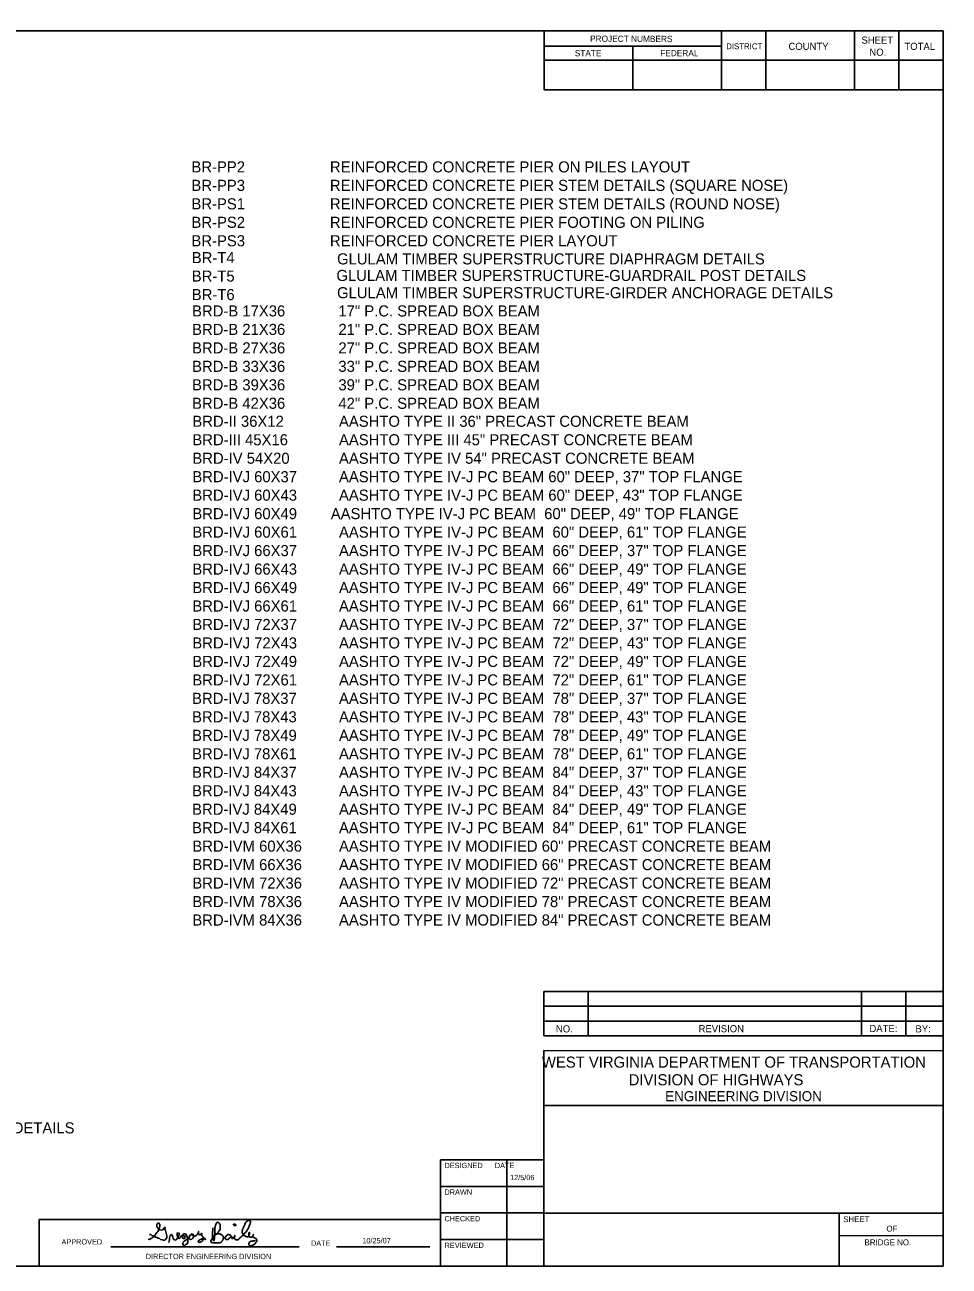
# Model space of a CAD drawing. Extents: x 3383 to 3913, y -1011 to -674.
# Drawn here: x 3662.6 to 3912.7, y -1010.2 to -674.2 of the extents above; entities that cross this region are included whole.
import ezdxf

# ---------------------------------------------------------------- set-up
doc = ezdxf.new("R2010")
doc.units = 0
for name, color, linetype in [('14', 7, 'Continuous'), ('63', 7, 'Continuous'), ('Level 1', 7, 'Continuous'), ('Level 14', 7, 'Continuous'), ('text', 7, 'Continuous')]:
    doc.layers.add(name, color=color, linetype=linetype)

msp = doc.modelspace()

# ---------------------------------------------------------------- linework, layer by layer
at = {"layer": '14'}
for p, q in [((3407.12, -675.81), (3911.13, -675.83)), ((3803.13, -691.83), (3803.13, -675.81)), ((3851.12, -691.81), (3851.13, -675.81)), ((3863.12, -691.81), (3863.13, -675.81)), ((3887.13, -691.81), (3887.13, -675.83)), ((3899.12, -691.81), (3899.13, -675.83)), ((3911.13, -675.83), (3911.13, -1010.23)), ((3911.13, -691.81), (3911.13, -675.83)), ((3851.14, -680.02), (3803.14, -680.02)), ((3827.13, -691.81), (3827.14, -680.02)), ((3911.12, -683.83), (3803.13, -683.81)), ((3911.13, -691.81), (3803.13, -691.83)), ((3911.05, -935.91), (3803.03, -935.91)), ((3803.05, -935.91), (3803.05, -947.91)), ((3815.03, -935.91), (3815.05, -947.89)), ((3889.03, -935.89), (3889.05, -947.89)), ((3901.05, -935.89), (3901.05, -947.89)), ((3911.05, -939.89), (3803.05, -939.89)), ((3911.05, -943.91), (3803.03, -943.91)), ((3911.03, -947.89), (3803.05, -947.91)), ((3911.05, -951.91), (3803.05, -951.89)), ((3803.05, -951.89), (3803.05, -1010.23)), ((3911.05, -966.73), (3803.05, -966.72)), ((3803.08, -981.43), (3775.09, -981.43)), ((3775.09, -981.43), (3775.09, -1010.23)), ((3793.09, -981.43), (3793.08, -1010.23)), ((3803.08, -988.63), (3775.08, -988.63)), ((3803.08, -995.83), (3775.08, -995.83)), ((3911.03, -995.91), (3803.05, -995.89)), ((3882.93, -995.83), (3882.93, -1010.23)), ((3803.08, -1003.03), (3775.08, -1003.03)), ((3911.05, -1001.99), (3883.05, -1001.97)), ((3911.13, -1010.23), (3407.09, -1010.22))]:
    msp.add_line(p, q, dxfattribs=at)
at = {"layer": '63'}
msp.add_line((3912.73, -674.23), (3912.73, -674.23), dxfattribs=at)
at = {"layer": 'Level 1'}
for p, q in [((3685.9, -1005.04), (3736.86, -1005.04)), ((3746.93, -1005.04), (3772.23, -1005.04))]:
    msp.add_line(p, q, dxfattribs=at)
for points in [[(3721.88, -1001.67), (3721.98, -1001.51), (3722.08, -1001.36), (3722.18, -1001.21), (3722.3, -1001.08), (3722.45, -1000.98), (3722.57, -1000.84), (3722.67, -1000.68), (3722.75, -1000.51), (3722.87, -1000.34), (3722.97, -1000.17), (3723.04, -1000.01), (3723.14, -999.82), (3723.22, -999.64), (3723.31, -999.45), (3723.37, -999.28), (3723.44, -999.12), (3723.51, -998.95), (3723.56, -998.77), (3723.62, -998.6), (3723.66, -998.41), (3723.69, -998.23), (3723.66, -998.04), (3723.54, -997.91), (3723.37, -997.84), (3723.19, -997.81), (3723.02, -997.91), (3722.87, -998.01), (3722.7, -998.08), (3722.57, -998.2), (3722.47, -998.35), (3722.37, -998.5), (3722.23, -998.63), (3722.2, -998.82), (3722.13, -998.98), (3722.06, -999.15), (3721.96, -999.3), (3721.9, -999.47), (3721.8, -999.62), (3721.76, -999.8), (3721.66, -999.96), (3721.63, -1000.14), (3721.56, -1000.32), (3721.49, -1000.51), (3721.43, -1000.68), (3721.43, -1000.86), (3721.43, -1001.05), (3721.46, -1001.23), (3721.54, -1001.4), (3721.61, -1001.58), (3721.7, -1001.75), (3721.83, -1001.87), (3722, -1001.93), (3722.15, -1002.05), (3722.33, -1002.08), (3722.5, -1002.19), (3722.67, -1002.25), (3722.87, -1002.27), (3723.05, -1002.27), (3723.15, -1002.12), (3723.26, -1001.97), (3723.34, -1001.78), (3723.41, -1001.6), (3723.42, -1001.41), (3723.47, -1001.21), (3723.34, -1001.1), (3723.27, -1001.28), (3723.2, -1001.45), (3723.2, -1001.63), (3723.2, -1001.82), (3723.2, -1002), (3723.27, -1002.19), (3723.44, -1002.29), (3723.61, -1002.35), (3723.79, -1002.37), (3723.98, -1002.37), (3724.14, -1002.3), (3724.24, -1002.14), (3724.36, -1002), (3724.45, -1001.82), (3724.5, -1001.63), (3724.41, -1001.82), (3724.35, -1001.98), (3724.28, -1002.15), (3724.35, -1002.32), (3724.51, -1002.4), (3724.68, -1002.49), (3724.8, -1002.62), (3724.98, -1002.67), (3725.17, -1002.74), (3725.28, -1002.87), (3725.35, -1003.04), (3725.42, -1003.21), (3725.42, -1003.39), (3725.38, -1003.58), (3725.25, -1003.69), (3725.15, -1003.85), (3725.02, -1004), (3724.92, -1004.15), (3724.75, -1004.26), (3724.61, -1004.38), (3724.45, -1004.48), (3724.28, -1004.58), (3724.13, -1004.68), (3723.93, -1004.7), (3723.74, -1004.72), (3723.56, -1004.72), (3723.39, -1004.62), (3723.29, -1004.47), (3723.26, -1004.28), (3723.27, -1004.1), (3723.32, -1003.91), (3723.42, -1003.74), (3723.54, -1003.61), (3723.71, -1003.54), (3723.88, -1003.48), (3724.06, -1003.44), (3724.24, -1003.44), (3724.43, -1003.41), (3724.61, -1003.41), (3724.8, -1003.38), (3724.98, -1003.34), (3725.08, -1003.31)], [(3695.98, -1002.91), (3696.39, -1002.97), (3696.65, -1002.85), (3696.99, -1002.64), (3697.26, -1002.37), (3697.59, -1002.17), (3697.9, -1001.87), (3698.06, -1001.46), (3698.3, -1001.16), (3698.6, -1000.89), (3698.83, -1000.56), (3699, -1000.19), (3699.07, -999.75), (3699.14, -999.35), (3699.17, -998.95), (3698.93, -998.55), (3698.57, -998.55), (3698.36, -998.85), (3698.3, -999.22), (3698.3, -999.62), (3698.57, -999.89), (3698.8, -1000.22), (3699.14, -1000.43), (3699.57, -1000.46), (3699.94, -1000.39), (3700.18, -1000.09), (3700.41, -999.72), (3700.61, -999.85), (3700.54, -1000.22), (3700.65, -1000.59), (3700.78, -1000.93), (3700.91, -1001.26), (3700.98, -1001.67), (3701.05, -1002.07), (3701.05, -1002.47), (3700.81, -1002.91), (3700.54, -1003.17), (3700.11, -1003.17), (3699.77, -1003.08), (3699.37, -1002.97), (3699.04, -1002.77), (3698.7, -1002.69), (3698.33, -1002.5), (3697.96, -1002.37), (3697.66, -1002.17), (3697.33, -1002.03), (3696.99, -1001.9), (3696.69, -1001.7), (3696.35, -1001.63)], [(3701.59, -1003.81), (3701.69, -1003.43), (3701.74, -1003.06), (3701.79, -1002.69), (3701.86, -1002.32), (3701.99, -1001.95), (3702.21, -1001.65), (3702.5, -1001.87), (3702.67, -1002.37), (3702.73, -1002.74), (3702.97, -1003.01), (3703.45, -1003.19), (3703.72, -1002.94), (3703.96, -1002.64), (3704.17, -1002.35), (3704.29, -1002), (3704.43, -1001.65), (3704.38, -1001.28), (3703.89, -1001.21), (3703.89, -1001.58), (3703.89, -1001.95), (3703.94, -1002.32), (3704.07, -1002.67), (3704.49, -1002.71), (3704.73, -1002.44), (3704.85, -1002.07), (3705.18, -1001.92), (3705.55, -1001.92), (3705.97, -1002.24), (3705.85, -1002.71), (3705.48, -1002.74), (3705.28, -1002.44), (3705.3, -1002.05), (3705.42, -1001.68), (3705.73, -1001.51), (3706.1, -1001.45), (3706.4, -1001.88), (3706.51, -1002.25), (3706.61, -1002.6), (3706.72, -1002.96), (3706.77, -1003.33), (3706.77, -1003.71), (3706.51, -1004.16), (3706.22, -1004.4), (3705.9, -1004.6), (3705.53, -1004.62), (3705.38, -1004.11), (3705.48, -1003.76), (3705.72, -1003.49), (3705.98, -1003.3), (3706.25, -1003.07), (3706.71, -1002.81), (3707.08, -1002.42), (3707.2, -1002.12), (3707.46, -1001.78), (3707.68, -1001.5), (3708.17, -1001.6), (3708.25, -1001.97), (3708.25, -1002.34), (3708.11, -1002.69), (3707.83, -1002.91), (3707.48, -1003.02), (3707.16, -1002.86), (3707.09, -1002.5), (3707.18, -1002.15), (3707.39, -1001.85), (3707.73, -1001.72), (3708.22, -1001.93), (3708.7, -1002.1), (3709.12, -1001.83), (3709.34, -1001.55), (3709.52, -1001.21), (3709.66, -1000.84), (3709.66, -1001.03), (3709.62, -1001.4), (3709.77, -1001.73), (3710.21, -1001.62), (3710.45, -1001.33), (3710.48, -1001.35), (3710.43, -1001.72), (3710.63, -1002.05), (3710.9, -1002.3), (3710.91, -1002.67), (3710.91, -1003.04), (3710.71, -1003.34), (3710.45, -1003.59), (3710.09, -1003.74), (3709.74, -1003.83), (3709.52, -1003.54), (3709.76, -1003.23), (3710.08, -1003.01), (3710.45, -1002.94), (3710.75, -1002.74), (3711.27, -1002.64), (3711.54, -1003.06), (3711.57, -1003.04)], [(3713.45, -999.89), (3713.46, -1000.07), (3713.46, -1000.26), (3713.46, -1000.44), (3713.46, -1000.64), (3713.43, -1000.83), (3713.4, -1001.01), (3713.4, -1001.2), (3713.4, -1001.38), (3713.4, -1001.57), (3713.41, -1001.75), (3713.43, -1001.93), (3713.43, -1002.12), (3713.45, -1002.3), (3713.48, -1002.49), (3713.5, -1002.69), (3713.51, -1002.87), (3713.56, -1003.06), (3713.68, -1003.19), (3713.78, -1003.34), (3713.83, -1003.16), (3713.9, -1002.99), (3713.95, -1002.81), (3713.97, -1002.62), (3713.97, -1002.44), (3713.97, -1002.25), (3713.98, -1002.07), (3713.98, -1001.88), (3714, -1001.7), (3714.02, -1001.51), (3714.03, -1001.33), (3714.03, -1001.15), (3714.03, -1000.96), (3714.03, -1000.78), (3714.03, -1000.59), (3714.03, -1000.41), (3714.03, -1000.22), (3714.05, -1000.04), (3714.08, -999.85), (3714.12, -999.65), (3714.17, -999.47), (3714.22, -999.28), (3714.23, -999.1), (3714.3, -998.93), (3714.37, -998.77), (3714.44, -998.6), (3714.54, -998.43), (3714.7, -998.36), (3714.89, -998.38), (3715.07, -998.43), (3715.19, -998.56), (3715.27, -998.73), (3715.37, -998.88), (3715.46, -999.05), (3715.49, -999.23), (3715.51, -999.42), (3715.51, -999.6), (3715.51, -999.79), (3715.51, -999.97), (3715.51, -1000.16), (3715.48, -1000.34), (3715.37, -1000.49), (3715.24, -1000.61), (3715.12, -1000.74), (3715.06, -1000.91), (3714.96, -1001.06), (3714.85, -1001.21), (3714.79, -1001.38), (3714.64, -1001.48), (3714.47, -1001.57), (3714.32, -1001.68), (3714.15, -1001.78), (3714.02, -1001.9), (3713.88, -1002.03), (3713.78, -1002.19), (3713.65, -1002.3), (3713.55, -1002.45), (3713.45, -1002.6), (3713.31, -1002.76), (3713.21, -1002.91), (3713.14, -1003.07), (3713.04, -1003.23), (3712.98, -1003.39), (3712.94, -1003.58), (3713.01, -1003.74), (3713.18, -1003.81), (3713.36, -1003.83), (3713.55, -1003.88), (3713.73, -1003.91), (3713.92, -1003.93), (3714.1, -1003.93), (3714.3, -1003.93), (3714.49, -1003.93), (3714.67, -1003.93), (3714.85, -1003.93), (3715.04, -1003.93), (3715.22, -1003.93), (3715.41, -1003.93), (3715.54, -1003.8), (3715.71, -1003.73), (3715.86, -1003.63), (3716.01, -1003.49), (3716.08, -1003.33), (3716.15, -1003.16), (3716.25, -1003.01), (3716.31, -1002.84), (3716.36, -1002.66), (3716.4, -1002.47), (3716.4, -1002.29), (3716.28, -1002.15), (3716.15, -1002.03), (3716.01, -1001.9), (3715.89, -1001.75), (3715.73, -1001.65), (3715.56, -1001.55), (3715.37, -1001.51), (3715.19, -1001.48), (3715.01, -1001.45), (3714.8, -1001.45), (3714.6, -1001.45), (3714.42, -1001.45), (3714.23, -1001.41), (3714.23, -1001.41)], [(3719.2, -998.92), (3719.2, -999.1), (3719.33, -999.22), (3719.52, -999.27), (3719.7, -999.25), (3719.73, -999.07), (3719.6, -998.95), (3719.47, -998.82), (3719.28, -998.82), (3719.11, -998.88), (3719.11, -999)], [(3718.68, -1002.89), (3718.71, -1002.71), (3718.71, -1002.52), (3718.71, -1002.34), (3718.56, -1002.2), (3718.43, -1002.07), (3718.33, -1001.92), (3718.17, -1001.82), (3718.02, -1001.72), (3717.86, -1001.65), (3717.67, -1001.65), (3717.49, -1001.72), (3717.35, -1001.83), (3717.2, -1001.95), (3717.07, -1002.07), (3716.97, -1002.22), (3716.9, -1002.39), (3716.8, -1002.54), (3716.73, -1002.71), (3716.85, -1002.84), (3716.97, -1002.97), (3717.17, -1003.02), (3717.35, -1003.02), (3717.54, -1003.02), (3717.71, -1002.96), (3717.82, -1002.81), (3717.94, -1002.67), (3718.06, -1002.52), (3718.23, -1002.42), (3718.43, -1002.42), (3718.63, -1002.44), (3718.8, -1002.5), (3718.96, -1002.57), (3719.11, -1002.67), (3719.3, -1002.67), (3719.35, -1002.49), (3719.4, -1002.3), (3719.42, -1002.1), (3719.42, -1001.92), (3719.35, -1002.08), (3719.31, -1002.27), (3719.31, -1002.45), (3719.31, -1002.64), (3719.33, -1002.82), (3719.5, -1002.91), (3719.67, -1003.01), (3719.85, -1003.06), (3720.04, -1003.07), (3720.22, -1003.07), (3720.4, -1003.04), (3720.56, -1002.94), (3720.66, -1002.77), (3720.79, -1002.66), (3720.89, -1002.49), (3721.03, -1002.37), (3721.18, -1002.27), (3721.31, -1002.14), (3721.44, -1002), (3721.6, -1001.9), (3721.75, -1001.8), (3721.85, -1001.67)]]:
    msp.add_lwpolyline(points, dxfattribs=at)
at = {"layer": 'Level 14'}
for p, q in [((3666.47, -997.6), (3666.47, -1010.22)), ((3775.09, -997.61), (3666.47, -997.6))]:
    msp.add_line(p, q, dxfattribs=at)

# ---------------------------------------------------------------- texts
at = {"layer": '14'}
for s, height, rotation, p in [('PROJECT NUMBERS', 1.6773, 359.8097, (3815.57, -678.82)), ('SHEET', 1.919, 359.8929, (3889.01, -679.32)), ('STATE', 1.675, 0.1193, (3811.44, -682.74)), ('FEDERAL', 1.675, 359.9983, (3834.56, -682.72)), ('DISTRICT', 1.582, 359.907, (3852.41, -680.82)), ('COUNTY', 1.919, 359.9983, (3869.25, -681.01)), ('NO.', 1.925, 359.9983, (3891.15, -682.6)), ('TOTAL', 1.919, 359.9983, (3900.64, -681.01)), ('NO.', 1.925, 359.9983, (3806.33, -946.96)), ('REVISION', 1.925, 359.9983, (3844.92, -946.92)), ('DATE:', 1.925, 359.9983, (3891.16, -946.87)), ('BY:', 1.925, 359.9983, (3903.61, -946.95)), (' WEST VIRGINIA DEPARTMENT OF TRANSPORTATION', 3.0011, 359.9983, (3801.43, -956.5)), ('    DIVISION OF HIGHWAYS', 3.0011, 359.9983, (3821.56, -961.27)), ('ENGINEERING DIVISION', 2.7185, 359.9983, (3835.88, -965.57)), ('DESIGNED      DATE', 1.432, 359.9983, (3776.18, -983.69)), ('12/5/06', 1.432, 359.9983, (3793.92, -986.94)), ('DRAWN', 1.432, 359.9983, (3776.18, -990.89)), ('CHECKED', 1.432, 359.9983, (3776.18, -998.09)), ('SHEET', 1.589, 359.9983, (3884.07, -998.31)), ('OF', 1.604, 359.9983, (3895.75, -1000.87)), ('10/25/07', 1.432, 359.9983, (3753.95, -1004.03)), ('REVIEWED', 1.447, 0.0944, (3776.18, -1005.31)), ('BRIDGE NO.', 1.604, 359.9983, (3889.83, -1004.59))]:
    msp.add_text(s, height=height, rotation=rotation, dxfattribs=at).set_placement(p)
at = {"layer": 'Level 14'}
for s, p in [('APPROVED', (3672.56, -1004.36)), ('DATE', (3740.06, -1004.72)), ('DIRECTOR ENGINEERING DIVISION', (3695.34, -1008.32))]:
    msp.add_text(s, height=1.432, rotation=359.9983, dxfattribs=at).set_placement(p)
at = {"layer": 'text'}
for s, height, p in [('BR-PP2', 3.001, (3707.71, -714.18)), (' REINFORCED CONCRETE PIER ON PILES LAYOUT', 3.0011, (3744.06, -714.18)), ('BR-PP3', 3.001, (3707.71, -719.18)), (' REINFORCED CONCRETE PIER STEM DETAILS (SQUARE NOSE)', 3.0011, (3744.06, -719.18)), ('BR-PS1', 3.001, (3707.71, -724.18)), (' REINFORCED CONCRETE PIER STEM DETAILS (ROUND NOSE)', 3.0011, (3744.06, -724.18)), ('BR-PS2', 3.001, (3707.71, -729.18)), (' REINFORCED CONCRETE PIER FOOTING ON PILING', 3.0011, (3744.06, -729.18)), ('BR-PS3', 3.001, (3707.71, -734.18)), (' REINFORCED CONCRETE PIER LAYOUT', 3.0011, (3744.06, -734.18)), ('BR-T4', 3.001, (3707.8, -738.74)), ('GLULAM TIMBER SUPERSTRUCTURE DIAPHRAGM DETAILS', 3.0011, (3747.11, -739.08)), ('BR-T5', 3.001, (3707.8, -743.74)), ('GLULAM TIMBER SUPERSTRUCTURE-GUARDRAIL POST DETAILS', 3.0011, (3746.94, -743.57)), ('BR-T6', 3.001, (3707.8, -748.74)), ('GLULAM TIMBER SUPERSTRUCTURE-GIRDER ANCHORAGE DETAILS', 3.0011, (3747.11, -748.24)), ('BRD-B 17X36', 3.0011, (3707.88, -753.17)), ('17" P.C. SPREAD BOX BEAM', 3.0011, (3747.47, -753.17)), ('BRD-B 21X36', 3.0011, (3707.88, -758.17)), ('21" P.C. SPREAD BOX BEAM', 3.0011, (3747.47, -758.17)), ('BRD-B 27X36', 3.0011, (3707.88, -763.17)), ('27" P.C. SPREAD BOX BEAM', 3.0011, (3747.47, -763.17)), ('BRD-B 33X36', 3.0011, (3707.88, -768.17)), ('33" P.C. SPREAD BOX BEAM', 3.0011, (3747.47, -768.17)), ('BRD-B 39X36', 3.0011, (3707.88, -773.17)), ('39" P.C. SPREAD BOX BEAM', 3.0011, (3747.47, -773.17)), ('BRD-B 42X36', 3.0011, (3707.88, -778.17)), ('42" P.C. SPREAD BOX BEAM', 3.0011, (3747.47, -778.17)), ('BRD-II 36X12', 3.0011, (3707.95, -783.04)), ('AASHTO TYPE II 36" PRECAST CONCRETE BEAM', 3.0011, (3747.63, -783.04)), ('BRD-III 45X16', 3.0011, (3707.95, -788.04)), ('AASHTO TYPE III 45" PRECAST CONCRETE BEAM', 3.0011, (3747.63, -788.04)), ('BRD-IV 54X20', 3.0011, (3707.95, -793.04)), ('AASHTO TYPE IV 54" PRECAST CONCRETE BEAM', 3.0011, (3747.63, -793.04)), ('BRD-IVJ 60X37', 3.0011, (3707.95, -798.04)), ('AASHTO TYPE IV-J PC BEAM 60" DEEP, 37" TOP FLANGE', 3.0011, (3747.63, -798.04)), ('BRD-IVJ 60X43', 3.0011, (3707.95, -803.04)), ('AASHTO TYPE IV-J PC BEAM 60" DEEP, 43" TOP FLANGE', 3.0011, (3747.63, -803.04)), ('BRD-IVJ 60X49', 3.0011, (3707.95, -808.04)), (' AASHTO TYPE IV-J PC BEAM  60" DEEP, 49" TOP FLANGE', 3.0011, (3744.29, -808.04)), ('BRD-IVJ 60X61', 3.0011, (3707.95, -813.04)), ('AASHTO TYPE IV-J PC BEAM  60" DEEP, 61" TOP FLANGE', 3.0011, (3747.63, -813.04)), ('BRD-IVJ 66X37', 3.0011, (3707.95, -818.04)), ('AASHTO TYPE IV-J PC BEAM  66" DEEP, 37" TOP FLANGE', 3.0011, (3747.63, -818.04)), ('BRD-IVJ 66X43', 3.0011, (3707.95, -823.04)), ('AASHTO TYPE IV-J PC BEAM  66" DEEP, 49" TOP FLANGE', 3.0011, (3747.63, -823.04)), ('BRD-IVJ 66X49', 3.0011, (3707.95, -828.04)), ('AASHTO TYPE IV-J PC BEAM  66" DEEP, 49" TOP FLANGE', 3.0011, (3747.63, -828.04)), ('BRD-IVJ 66X61', 3.0011, (3707.95, -833.04)), ('AASHTO TYPE IV-J PC BEAM  66" DEEP, 61" TOP FLANGE', 3.0011, (3747.63, -833.04)), ('BRD-IVJ 72X37', 3.0011, (3707.95, -838.04)), ('AASHTO TYPE IV-J PC BEAM  72" DEEP, 37" TOP FLANGE', 3.0011, (3747.63, -838.04)), ('BRD-IVJ 72X43', 3.0011, (3707.95, -843.04)), ('AASHTO TYPE IV-J PC BEAM  72" DEEP, 43" TOP FLANGE', 3.0011, (3747.63, -843.04)), ('BRD-IVJ 72X49', 3.0011, (3707.95, -848.04)), ('AASHTO TYPE IV-J PC BEAM  72" DEEP, 49" TOP FLANGE', 3.0011, (3747.63, -848.04)), ('BRD-IVJ 72X61', 3.0011, (3707.95, -853.04)), ('AASHTO TYPE IV-J PC BEAM  72" DEEP, 61" TOP FLANGE', 3.0011, (3747.63, -853.04)), ('BRD-IVJ 78X37', 3.0011, (3707.88, -858.04)), ('AASHTO TYPE IV-J PC BEAM  78" DEEP, 37" TOP FLANGE', 3.0011, (3747.63, -858.04)), ('BRD-IVJ 78X43', 3.0011, (3707.88, -863.04)), ('AASHTO TYPE IV-J PC BEAM  78" DEEP, 43" TOP FLANGE', 3.0011, (3747.63, -863.04)), ('BRD-IVJ 78X49', 3.0011, (3707.88, -868.04)), ('AASHTO TYPE IV-J PC BEAM  78" DEEP, 49" TOP FLANGE', 3.0011, (3747.63, -868.04)), ('BRD-IVJ 78X61', 3.0011, (3707.88, -873.04)), ('AASHTO TYPE IV-J PC BEAM  78" DEEP, 61" TOP FLANGE', 3.0011, (3747.63, -873.04)), ('BRD-IVJ 84X37', 3.0011, (3707.88, -878.04)), ('AASHTO TYPE IV-J PC BEAM  84" DEEP, 37" TOP FLANGE', 3.0011, (3747.63, -878.04)), ('BRD-IVJ 84X43', 3.0011, (3707.88, -883.04)), ('AASHTO TYPE IV-J PC BEAM  84" DEEP, 43" TOP FLANGE', 3.0011, (3747.63, -883.04)), ('BRD-IVJ 84X49', 3.0011, (3707.88, -888.04)), ('AASHTO TYPE IV-J PC BEAM  84" DEEP, 49" TOP FLANGE', 3.0011, (3747.63, -888.04)), ('BRD-IVJ 84X61', 3.0011, (3707.88, -893.04)), ('AASHTO TYPE IV-J PC BEAM  84" DEEP, 61" TOP FLANGE', 3.0011, (3747.63, -893.04)), ('BRD-IVM 60X36', 3.0011, (3707.95, -898.04)), ('AASHTO TYPE IV MODIFIED 60" PRECAST CONCRETE BEAM', 3.0011, (3747.63, -898.04)), ('BRD-IVM 66X36', 3.0011, (3707.95, -903.04)), ('AASHTO TYPE IV MODIFIED 66" PRECAST CONCRETE BEAM', 3.0011, (3747.63, -903.04)), ('BRD-IVM 72X36', 3.0011, (3707.95, -908.04)), ('AASHTO TYPE IV MODIFIED 72" PRECAST CONCRETE BEAM', 3.0011, (3747.63, -908.04)), ('BRD-IVM 78X36', 3.0011, (3707.95, -913.04)), ('AASHTO TYPE IV MODIFIED 78" PRECAST CONCRETE BEAM', 3.0011, (3747.63, -913.04)), ('BRD-IVM 84X36', 3.0011, (3707.95, -918.04)), ('AASHTO TYPE IV MODIFIED 84" PRECAST CONCRETE BEAM', 3.0011, (3747.63, -918.04)), ('PRESTRESSED CONCRETE BEAM SKEWED END REINFORCING MISC. DESIGN AND ASSEMBLY DETAILS', 3.0011, (3473.82, -974.29))]:
    msp.add_text(s, height=height, dxfattribs=at).set_placement(p)

doc.saveas('drawing.dxf')
